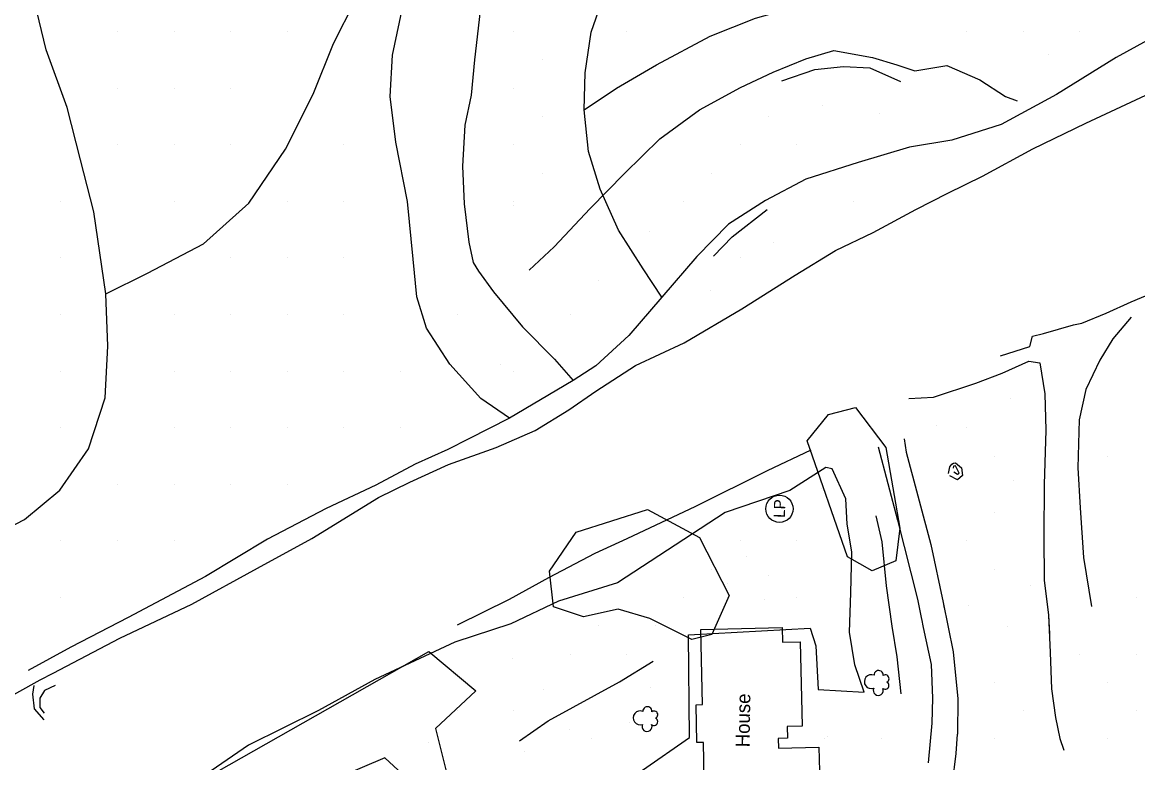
# Model space of a CAD drawing. Extents: x 19528164 to 19545171, y 7585743 to 7602745.
# Drawn here: x 19531341.3 to 19531735.5, y 7587906.6 to 7588168.3 of the extents above; entities that cross this region are included whole.
import ezdxf

# ---------------------------------------------------------------- set-up
doc = ezdxf.new("R2010")
doc.units = 0
for name, color, linetype in [('PhoBreakLine', 7, 'Continuous'), ('PhoBuilding', 7, 'Continuous'), ('PhoISAEPoints', 7, 'Continuous'), ('PhoNotesDesign', 7, 'Continuous'), ('PhoVegetation', 7, 'Continuous'), ('SurBreakLine', 7, 'Continuous'), ('SurEdgeEntranceUnpaved', 7, 'Continuous'), ('SurNaturalCells', 7, 'Continuous'), ('SurROWRail', 7, 'Continuous')]:
    doc.layers.add(name, color=color, linetype=linetype)

# ---------------------------------------------------------------- blocks, each defined once
blk = doc.blocks.new('TRDC')
at = {"layer": 'PhoVegetation'}
for centre, radius, start, end in [((0.07, 3.96), 4.92, 338.20507, 201.79492), ((-5.96, -1.07), 3.52, 65.4824, 294.51753), ((4.86, -1.07), 3.21, 265.99819, 94.00181), ((-2.37, -5.89), 2.68, 142.75014, 335.32234), ((2.46, -5.82), 2.67, 206.52416, 35.40334)]:
    blk.add_arc(centre, radius, start, end, dxfattribs=at)

msp = doc.modelspace()

# ---------------------------------------------------------------- linework, layer by layer
at = {"layer": 'PhoBreakLine'}
for points in [[(19531527.73, 7588330.92), (19531526.84, 7588308.57), (19531524.49, 7588288.8), (19531521.79, 7588272.16), (19531517.23, 7588259.83), (19531515.24, 7588245.82), (19531511.48, 7588228.57), (19531508.26, 7588209.27), (19531504.25, 7588191.15), (19531503.15, 7588172.41), (19531501.14, 7588154.99), (19531500, 7588142.58), (19531497.71, 7588131.99), (19531496.87, 7588117.42), (19531497.45, 7588104.2), (19531499.13, 7588090.6), (19531500.71, 7588083.37), (19531502.52, 7588080.39), (19531507.82, 7588073.06), (19531518.11, 7588060.7), (19531529.45, 7588049.23), (19531536, 7588041.67)], [(19531370.86, 7588072.31), (19531385.53, 7588079.64), (19531405.43, 7588090.02), (19531421.42, 7588104.33), (19531434.4, 7588123.43), (19531444.16, 7588142.9), (19531451.37, 7588160.83), (19531458.95, 7588175.94), (19531466.04, 7588196.76), (19531468.16, 7588214.32), (19531469.32, 7588233.55), (19531469.81, 7588263.92), (19531470.17, 7588291.27), (19531469.8, 7588322.57)], [(19531567.38, 7588071.15), (19531560.7, 7588081.13), (19531552.06, 7588094.84), (19531545.52, 7588109.33), (19531541.39, 7588122.61), (19531539.86, 7588137.36), (19531540.21, 7588150.48), (19531542.35, 7588164.87), (19531547.72, 7588180.18), (19531552.98, 7588192.45), (19531559.17, 7588206.45), (19531565.8, 7588221.16), (19531572.49, 7588234.58), (19531578.67, 7588247.53), (19531582.51, 7588261.6), (19531584.6, 7588275.01), (19531587.12, 7588293.68), (19531588.52, 7588309.68)], [(19531513.5, 7588028.38), (19531503.34, 7588035.36), (19531492.48, 7588047.49), (19531484.15, 7588060.24), (19531480.78, 7588071.27), (19531479.44, 7588084.54), (19531477.5, 7588105.01), (19531473.38, 7588125.91), (19531471.34, 7588142.02), (19531472.15, 7588156.66), (19531475.43, 7588172.28), (19531480.35, 7588185.19), (19531482.76, 7588201.64), (19531484.12, 7588217.98), (19531485.17, 7588232.83)], [(19531092.92, 7587957.88), (19531110.69, 7587961.65), (19531134.32, 7587962.81), (19531165.71, 7587959.59), (19531188.95, 7587956.79), (19531207.79, 7587956.86), (19531227.96, 7587957.55), (19531244.89, 7587960.67), (19531269.25, 7587963.81), (19531295.54, 7587972.59), (19531323.84, 7587983.09), (19531342.16, 7587992.58), (19531354.61, 7588002.92), (19531364.74, 7588017.58), (19531370.6, 7588035.52), (19531371.52, 7588053.78), (19531370.86, 7588072.31), (19531366.62, 7588101.27), (19531361.88, 7588119.7), (19531357.22, 7588138.19), (19531349.78, 7588158.61), (19531343.88, 7588183.09)], [(19531539.86, 7588137.36), (19531551.33, 7588145.08), (19531565.46, 7588153.26), (19531584.4, 7588163.45), (19531600.39, 7588169.76), (19531613.56, 7588173.45), (19531619.59, 7588171.24)], [(19531749.8, 7588167.85), (19531727.91, 7588155.83), (19531706.8, 7588142.73), (19531687.26, 7588132.17), (19531669.82, 7588126.67), (19531654.84, 7588124.15), (19531636.73, 7588118.73), (19531618.27, 7588112.88), (19531604.03, 7588105.3), (19531590.86, 7588096.96), (19531579.68, 7588085.54), (19531567.38, 7588071.15), (19531555.64, 7588057.59), (19531544.05, 7588046.94), (19531536, 7588041.67), (19531524.48, 7588034.88), (19531513.5, 7588028.38), (19531499.16, 7588021.13), (19531491.69, 7588017.29), (19531480.23, 7588012.09), (19531466.27, 7588004.68), (19531448.74, 7587996.51), (19531428.05, 7587985.65), (19531406.1, 7587972.41), (19531378.75, 7587957.97), (19531358.45, 7587947.42), (19531343.46, 7587939.15)], [(19531520.5, 7588080.69), (19531529.25, 7588088.95), (19531541.98, 7588102.54), (19531554.17, 7588114.9), (19531566.64, 7588127.16), (19531580.71, 7588137.4), (19531595.19, 7588145.26), (19531606.69, 7588150.67), (19531618.22, 7588155.44), (19531628.18, 7588158.33), (19531641.84, 7588155.9), (19531650.38, 7588153.28), (19531656.79, 7588151.16), (19531668.04, 7588153.02), (19531679.75, 7588147.96), (19531688.78, 7588142.06), (19531692.95, 7588140.54)], [(19531609.69, 7588147.63), (19531621.41, 7588151.58), (19531631.55, 7588152.64), (19531640.82, 7588152.17), (19531651.67, 7588147.36)], [(19531331.1, 7587926.76), (19531347.67, 7587935.95), (19531352.28, 7587938.27), (19531375.83, 7587950.64), (19531401.28, 7587962.67), (19531424.44, 7587975.37), (19531443.6, 7587985.9), (19531467.22, 7588000.31), (19531478.27, 7588005.75), (19531491.91, 7588012.03), (19531508.77, 7588017.97), (19531522.55, 7588024.08), (19531534.46, 7588031.36), (19531543.97, 7588037.97), (19531557.98, 7588047.03), (19531575.24, 7588055.06), (19531595.6, 7588066.99), (19531614.47, 7588078.92), (19531628.67, 7588087.62), (19531642.02, 7588094.01), (19531657.06, 7588102.11), (19531668.43, 7588107.96), (19531680.71, 7588113.91), (19531698.4, 7588123.57), (19531717.21, 7588132.67), (19531738.36, 7588142.52)], [(19531585.55, 7588085.59), (19531592.22, 7588092.47), (19531604.59, 7588102.16)], [(19531687.06, 7588050.36), (19531697.39, 7588053.73), (19531698.32, 7588057.38), (19531702.27, 7588058.27), (19531712.82, 7588061.35), (19531715.75, 7588061.94), (19531724.37, 7588065.46), (19531733.24, 7588069.54), (19531741.88, 7588073.12)], [(19531733.22, 7588064.14), (19531726.73, 7588056.41), (19531722.14, 7588048.93), (19531717.16, 7588038.47), (19531714.83, 7588027.82), (19531714.37, 7588010.89), (19531715.14, 7587996.67), (19531716.37, 7587979.12), (19531719.21, 7587961.83)], [(19531733.22, 7588064.14), (19531726.73, 7588056.41), (19531722.14, 7588048.93), (19531717.16, 7588038.47), (19531714.83, 7588027.82), (19531714.37, 7588010.89), (19531715.14, 7587996.67), (19531716.37, 7587979.12), (19531719.21, 7587961.83)], [(19531654.61, 7588035.28), (19531663.31, 7588035.83), (19531678.31, 7588040.79), (19531687.57, 7588044.33), (19531697, 7588048.51), (19531700.92, 7588047.97), (19531702.65, 7588037), (19531703.07, 7588024.09), (19531702.43, 7588004.96), (19531702.36, 7587986.51), (19531702.5, 7587971.1), (19531704, 7587958.75), (19531704.29, 7587952.2)], [(19531495.15, 7587955.4), (19531513.5, 7587964.42), (19531527.4, 7587972.03), (19531543.82, 7587980.64), (19531555.11, 7587985.8), (19531579.3, 7587997.31), (19531604.65, 7588009.91), (19531620.07, 7588017.22)], [(19531560.46, 7587903.96), (19531577.16, 7587915.53), (19531576.76, 7587951.77), (19531619.75, 7587954.21), (19531621.78, 7587947.93), (19531622.6, 7587932.47), (19531638.86, 7587931.55), (19531635.52, 7587941.24), (19531633.7, 7587952.79), (19531634.1, 7587966.65), (19531634.49, 7587981.17), (19531632.89, 7587990.96), (19531632.42, 7587999.82), (19531627.56, 7588010.51), (19531625.35, 7588010.9), (19531612.58, 7588002.84), (19531589.69, 7587995.06), (19531551.66, 7587970.24), (19531530.78, 7587963.71), (19531513.98, 7587955.69), (19531494.19, 7587949.26), (19531465.95, 7587935.98), (19531446.03, 7587925.01), (19531421.29, 7587912.82), (19531383.18, 7587886.71)], [(19531668.65, 7588008.87), (19531669.06, 7588011.16), (19531669.87, 7588012.11), (19531670.44, 7588012.48), (19531671.06, 7588012.62), (19531673.2, 7588010.84), (19531673.55, 7588008.07), (19531671.86, 7588006.59), (19531669.13, 7588008)], [(19531670.49, 7588009.37), (19531671.81, 7588008.59), (19531672.43, 7588008.99), (19531671.16, 7588011.57), (19531670.41, 7588011.37), (19531670.29, 7588010.7)], [(19531643.01, 7587993.92), (19531645.1, 7587984.64), (19531646.65, 7587969.11), (19531648.63, 7587954.88), (19531650.44, 7587944), (19531651.81, 7587930.96)], [(19531517.08, 7587914.33), (19531527.17, 7587921.46), (19531552.44, 7587935.23), (19531564.33, 7587942.45)], [(19531349.11, 7587921.72), (19531345.63, 7587925.71), (19531345.1, 7587930.78), (19531345.58, 7587933.89)], [(19531352.98, 7587933.92), (19531349.19, 7587932.08), (19531347.58, 7587929.41), (19531347.48, 7587926.08), (19531349.04, 7587924.14)]]:
    msp.add_lwpolyline(points, dxfattribs=at)
at = {"layer": 'PhoBuilding'}
msp.add_lwpolyline([(19531623.25, 7587895.17), (19531582.46, 7587894.23), (19531582.01, 7587913.76), (19531579.73, 7587913.71), (19531579.43, 7587927.12), (19531581.69, 7587927.17), (19531581.08, 7587953.69), (19531609.83, 7587954.34), (19531609.95, 7587949.18), (19531616.23, 7587949.33), (19531616.91, 7587919.54), (19531611.67, 7587919.42), (19531611.76, 7587915.24), (19531608.47, 7587915.17), (19531608.55, 7587911.8), (19531622.86, 7587912.13)], close=True, dxfattribs=at)
at = {"layer": 'PhoISAEPoints'}
for p, q in [((19531375, 7588165), (19531375, 7588165)), ((19531395, 7588165), (19531395, 7588165)), ((19531415, 7588165), (19531415, 7588165)), ((19531435, 7588165), (19531435, 7588165)), ((19531515, 7588165), (19531515, 7588165)), ((19531515, 7588165), (19531515, 7588165)), ((19531555, 7588165), (19531555, 7588165)), ((19531555, 7588165), (19531555, 7588165)), ((19531675, 7588165), (19531675, 7588165)), ((19531675, 7588165), (19531675, 7588165)), ((19531695, 7588165), (19531695, 7588165)), ((19531695, 7588165), (19531695, 7588165)), ((19531715, 7588165), (19531715, 7588165)), ((19531715, 7588165), (19531715, 7588165)), ((19531525, 7588155), (19531525, 7588155)), ((19531703.84, 7588157.06), (19531703.84, 7588157.06)), ((19531375, 7588145), (19531375, 7588145)), ((19531395, 7588145), (19531395, 7588145)), ((19531415, 7588145), (19531415, 7588145)), ((19531515, 7588145), (19531515, 7588145)), ((19531515, 7588145), (19531515, 7588145)), ((19531623.99, 7588138.85), (19531623.99, 7588138.85)), ((19531644.15, 7588135.96), (19531644.15, 7588135.96)), ((19531525, 7588135), (19531525, 7588135)), ((19531605, 7588135), (19531605, 7588135)), ((19531375, 7588125), (19531375, 7588125)), ((19531395, 7588125), (19531395, 7588125)), ((19531415, 7588125), (19531415, 7588125)), ((19531455, 7588125), (19531455, 7588125)), ((19531515, 7588125), (19531515, 7588125)), ((19531515, 7588125), (19531515, 7588125)), ((19531595, 7588125), (19531595, 7588125)), ((19531595, 7588125), (19531595, 7588125)), ((19531615, 7588125), (19531615, 7588125)), ((19531525, 7588115), (19531525, 7588115)), ((19531585, 7588115), (19531585, 7588115)), ((19531355, 7588105), (19531355, 7588105)), ((19531395, 7588105), (19531395, 7588105)), ((19531435, 7588105), (19531435, 7588105)), ((19531455, 7588105), (19531455, 7588105)), ((19531515, 7588105), (19531515, 7588105)), ((19531575, 7588105), (19531575, 7588105)), ((19531575, 7588105), (19531575, 7588105)), ((19531635, 7588105), (19531635, 7588105)), ((19531635, 7588105), (19531635, 7588105)), ((19531514.89, 7588103.46), (19531514.89, 7588103.46)), ((19531563, 7588094.49), (19531563, 7588094.49)), ((19531606.9, 7588090.55), (19531606.9, 7588090.55)), ((19531355, 7588085), (19531355, 7588085)), ((19531415, 7588085), (19531415, 7588085)), ((19531435, 7588085), (19531435, 7588085)), ((19531455, 7588085), (19531455, 7588085)), ((19531595, 7588085), (19531595, 7588085)), ((19531595, 7588085), (19531595, 7588085)), ((19531544.84, 7588076.88), (19531544.84, 7588076.88)), ((19531584.53, 7588073.65), (19531584.53, 7588073.65)), ((19531355, 7588065), (19531355, 7588065)), ((19531395, 7588065), (19531395, 7588065)), ((19531415, 7588065), (19531415, 7588065)), ((19531435, 7588065), (19531435, 7588065)), ((19531455, 7588065), (19531455, 7588065)), ((19531495, 7588065), (19531495, 7588065)), ((19531535, 7588065), (19531535, 7588065)), ((19531535, 7588065), (19531535, 7588065)), ((19531355, 7588045), (19531355, 7588045)), ((19531395, 7588045), (19531395, 7588045)), ((19531415, 7588045), (19531415, 7588045)), ((19531435, 7588045), (19531435, 7588045)), ((19531455, 7588045), (19531455, 7588045)), ((19531475, 7588045), (19531475, 7588045)), ((19531510.27, 7588047.39), (19531510.27, 7588047.39)), ((19531515, 7588045), (19531515, 7588045)), ((19531690.39, 7588035.29), (19531690.39, 7588035.29)), ((19531355, 7588025), (19531355, 7588025)), ((19531395, 7588025), (19531395, 7588025)), ((19531415, 7588025), (19531415, 7588025)), ((19531435, 7588025), (19531435, 7588025)), ((19531455, 7588025), (19531455, 7588025)), ((19531475, 7588025), (19531475, 7588025)), ((19531664.55, 7588025.75), (19531664.55, 7588025.75)), ((19531675, 7588025), (19531675, 7588025)), ((19531675, 7588025), (19531675, 7588025)), ((19531685, 7588015), (19531685, 7588015)), ((19531725, 7588015), (19531725, 7588015)), ((19531691.73, 7588006.43), (19531691.73, 7588006.43)), ((19531375, 7588005), (19531375, 7588005)), ((19531395, 7588005), (19531395, 7588005)), ((19531415, 7588005), (19531415, 7588005)), ((19531435, 7588005), (19531435, 7588005)), ((19531623.79, 7588003.46), (19531623.79, 7588003.46)), ((19531685, 7587995), (19531685, 7587995)), ((19531355, 7587985), (19531355, 7587985)), ((19531375, 7587985), (19531375, 7587985)), ((19531395, 7587985), (19531395, 7587985)), ((19531595, 7587985), (19531595, 7587985)), ((19531615, 7587985), (19531615, 7587985)), ((19531675, 7587985), (19531675, 7587985)), ((19531675, 7587985), (19531675, 7587985)), ((19531597.22, 7587979.47), (19531597.22, 7587979.47)), ((19531585, 7587975), (19531585, 7587975)), ((19531685, 7587975), (19531685, 7587975)), ((19531590.47, 7587969.81), (19531590.47, 7587969.81)), ((19531605.09, 7587972.92), (19531605.09, 7587972.92)), ((19531697.63, 7587969.3), (19531697.63, 7587969.3)), ((19531355, 7587965), (19531355, 7587965)), ((19531575, 7587965), (19531575, 7587965)), ((19531603.69, 7587964.25), (19531603.69, 7587964.25)), ((19531615, 7587965), (19531615, 7587965)), ((19531675.6, 7587962.14), (19531675.6, 7587962.14)), ((19531545, 7587955), (19531545, 7587955)), ((19531565, 7587955), (19531565, 7587955)), ((19531689.66, 7587954.67), (19531689.66, 7587954.67)), ((19531514.56, 7587943.48), (19531514.56, 7587943.48)), ((19531535, 7587945), (19531535, 7587945)), ((19531555, 7587945), (19531555, 7587945)), ((19531525.6, 7587932.65), (19531525.6, 7587932.65)), ((19531563.33, 7587933.3), (19531563.33, 7587933.3)), ((19531495, 7587925), (19531495, 7587925)), ((19531515, 7587925), (19531515, 7587925)), ((19531534.59, 7587918.45), (19531534.59, 7587918.45)), ((19531555.81, 7587920.82), (19531555.81, 7587920.82)), ((19531542.65, 7587915.24), (19531542.65, 7587915.24)), ((19531485.01, 7587913.77), (19531485.01, 7587913.77)), ((19531518.85, 7587910.51), (19531518.85, 7587910.51))]:
    msp.add_line(p, q, dxfattribs=at)
at = {"layer": 'PhoVegetation'}
for points in [[(19531632.99, 7587979.36), (19531618.71, 7588020.4), (19531626.24, 7588029.64), (19531635.78, 7588032.19), (19531646.48, 7588018.05), (19531651.42, 7587989.56), (19531650.02, 7587977.94), (19531641.63, 7587974.41)], [(19531563.06, 7587957.53), (19531551.93, 7587960.92), (19531539.71, 7587958.15), (19531529.1, 7587961.75), (19531527.62, 7587974.33), (19531537.09, 7587988.04), (19531562.26, 7587996.07), (19531580.65, 7587986.26), (19531591.13, 7587965.71), (19531585, 7587951.98), (19531577.93, 7587950.2)], [(19531385.5, 7587835.96), (19531388, 7587863.16), (19531383.58, 7587883.05), (19531383.08, 7587888.03), (19531485.01, 7587945.93), (19531501.61, 7587931.98), (19531487.35, 7587918.67), (19531491.92, 7587900.27), (19531489.83, 7587894.36), (19531483.33, 7587895.46), (19531469.49, 7587908.34), (19531416.7, 7587885.82), (19531419.81, 7587841.42), (19531411.79, 7587828.18), (19531398.38, 7587826.89)]]:
    msp.add_lwpolyline(points, close=True, dxfattribs=at)
at = {"layer": 'SurBreakLine'}
for points in [[(19531733.22, 7588064.14), (19531726.73, 7588056.41), (19531722.14, 7588048.93), (19531717.16, 7588038.47), (19531714.83, 7588027.82), (19531714.37, 7588010.89), (19531715.14, 7587996.67), (19531716.37, 7587979.12), (19531719.21, 7587961.83)], [(19531733.22, 7588064.14), (19531726.73, 7588056.41), (19531722.14, 7588048.93), (19531717.16, 7588038.47), (19531714.84, 7588027.82), (19531714.37, 7588010.89), (19531715.14, 7587996.67), (19531716.37, 7587979.12), (19531719.21, 7587961.83)], [(19531654.61, 7588035.28), (19531663.31, 7588035.83), (19531678.31, 7588040.79), (19531687.57, 7588044.33), (19531697, 7588048.51), (19531700.92, 7588047.97), (19531702.65, 7588037), (19531703.07, 7588024.09), (19531702.43, 7588004.96), (19531702.36, 7587986.51), (19531702.5, 7587971.1), (19531704, 7587958.75), (19531704.58, 7587945.53), (19531705, 7587932.73), (19531706.48, 7587922.53), (19531707.96, 7587915.22), (19531709.46, 7587911.07)], [(19531654.61, 7588035.28), (19531663.31, 7588035.83), (19531678.31, 7588040.79), (19531687.57, 7588044.33), (19531697, 7588048.51), (19531700.92, 7588047.97), (19531702.65, 7588037), (19531703.07, 7588024.09), (19531702.43, 7588004.96), (19531702.36, 7587986.51), (19531702.5, 7587971.1), (19531704, 7587958.75), (19531704.58, 7587945.53), (19531705, 7587932.73), (19531706.48, 7587922.53), (19531707.96, 7587915.22), (19531709.46, 7587911.07)], [(19531666.65, 7587963.82), (19531666.78, 7587963.22), (19531670.25, 7587945.8), (19531671.96, 7587929.18), (19531671.96, 7587929.18), (19531671.83, 7587916.68)], [(19531659.11, 7587957.49), (19531659.74, 7587954.42), (19531662.48, 7587941.28), (19531663.01, 7587929.43), (19531662.74, 7587920.57), (19531661.48, 7587906.61)]]:
    msp.add_lwpolyline(points, dxfattribs=at)
at = {"layer": 'SurEdgeEntranceUnpaved'}
for p, q in [((19531735, 7587965), (19531735, 7587965)), ((19531735, 7587965), (19531735, 7587965)), ((19531715, 7587945), (19531715, 7587945)), ((19531715, 7587945), (19531715, 7587945)), ((19531735, 7587945), (19531735, 7587945)), ((19531735, 7587945), (19531735, 7587945)), ((19531685, 7587935), (19531685, 7587935)), ((19531725, 7587935), (19531725, 7587935)), ((19531695, 7587925), (19531695, 7587925)), ((19531695, 7587925), (19531695, 7587925)), ((19531735, 7587925), (19531735, 7587925)), ((19531735, 7587925), (19531735, 7587925)), ((19531625, 7587915), (19531625, 7587915)), ((19531625.93, 7587915.78), (19531625.93, 7587915.78)), ((19531645, 7587915), (19531645, 7587915)), ((19531685, 7587915), (19531685, 7587915)), ((19531725, 7587915), (19531725, 7587915))]:
    msp.add_line(p, q, dxfattribs=at)
at = {"layer": 'SurNaturalCells'}
msp.add_circle((19531608.91, 7587996.35), 4.8, dxfattribs=at)
at = {"layer": 'SurROWRail'}
for points in [[(19531653.01, 7588021.13), (19531653.69, 7588016.34), (19531662.44, 7587983.75), (19531666.78, 7587963.22), (19531667.16, 7587961.29)], [(19531643.8, 7588018.25), (19531650.65, 7587992.36), (19531657.68, 7587964.42), (19531659.15, 7587957.3)], [(19531572.5, 7587850.62), (19531601.27, 7587853.33), (19531617.33, 7587851.1), (19531634.11, 7587852.07), (19531652.24, 7587855.18), (19531660.66, 7587865.35), (19531666.43, 7587883.68), (19531670.03, 7587899.26), (19531671.35, 7587909.9), (19531671.83, 7587916.68)]]:
    msp.add_lwpolyline(points, dxfattribs=at)

# ---------------------------------------------------------------- block references
at = {"layer": 'PhoVegetation', "xscale": 0.4999999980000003, "yscale": 0.49999999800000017, "rotation": 88.60949589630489}
for p in [(19531643.35, 7587935.17), (19531561.65, 7587922.38)]:
    msp.add_blockref('TRDC', p, dxfattribs=at)

# ---------------------------------------------------------------- texts
at = {"layer": 'PhoNotesDesign'}
msp.add_text('House', height=4.92, rotation=89.0083, dxfattribs=at).set_placement((19531598.32, 7587912.02))
at = {"layer": 'SurNaturalCells'}
msp.add_text('LP', height=3.999, rotation=88.6095, dxfattribs=at).set_placement((19531610.84, 7587993.13))

doc.saveas('drawing.dxf')
